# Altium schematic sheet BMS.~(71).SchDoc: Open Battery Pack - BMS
size A3; Date: 26/03/2019; Author: Morgane Vallée - Samuel Lesueur; Revision: 1.0; SheetNumber: 1; SheetTotal: 3
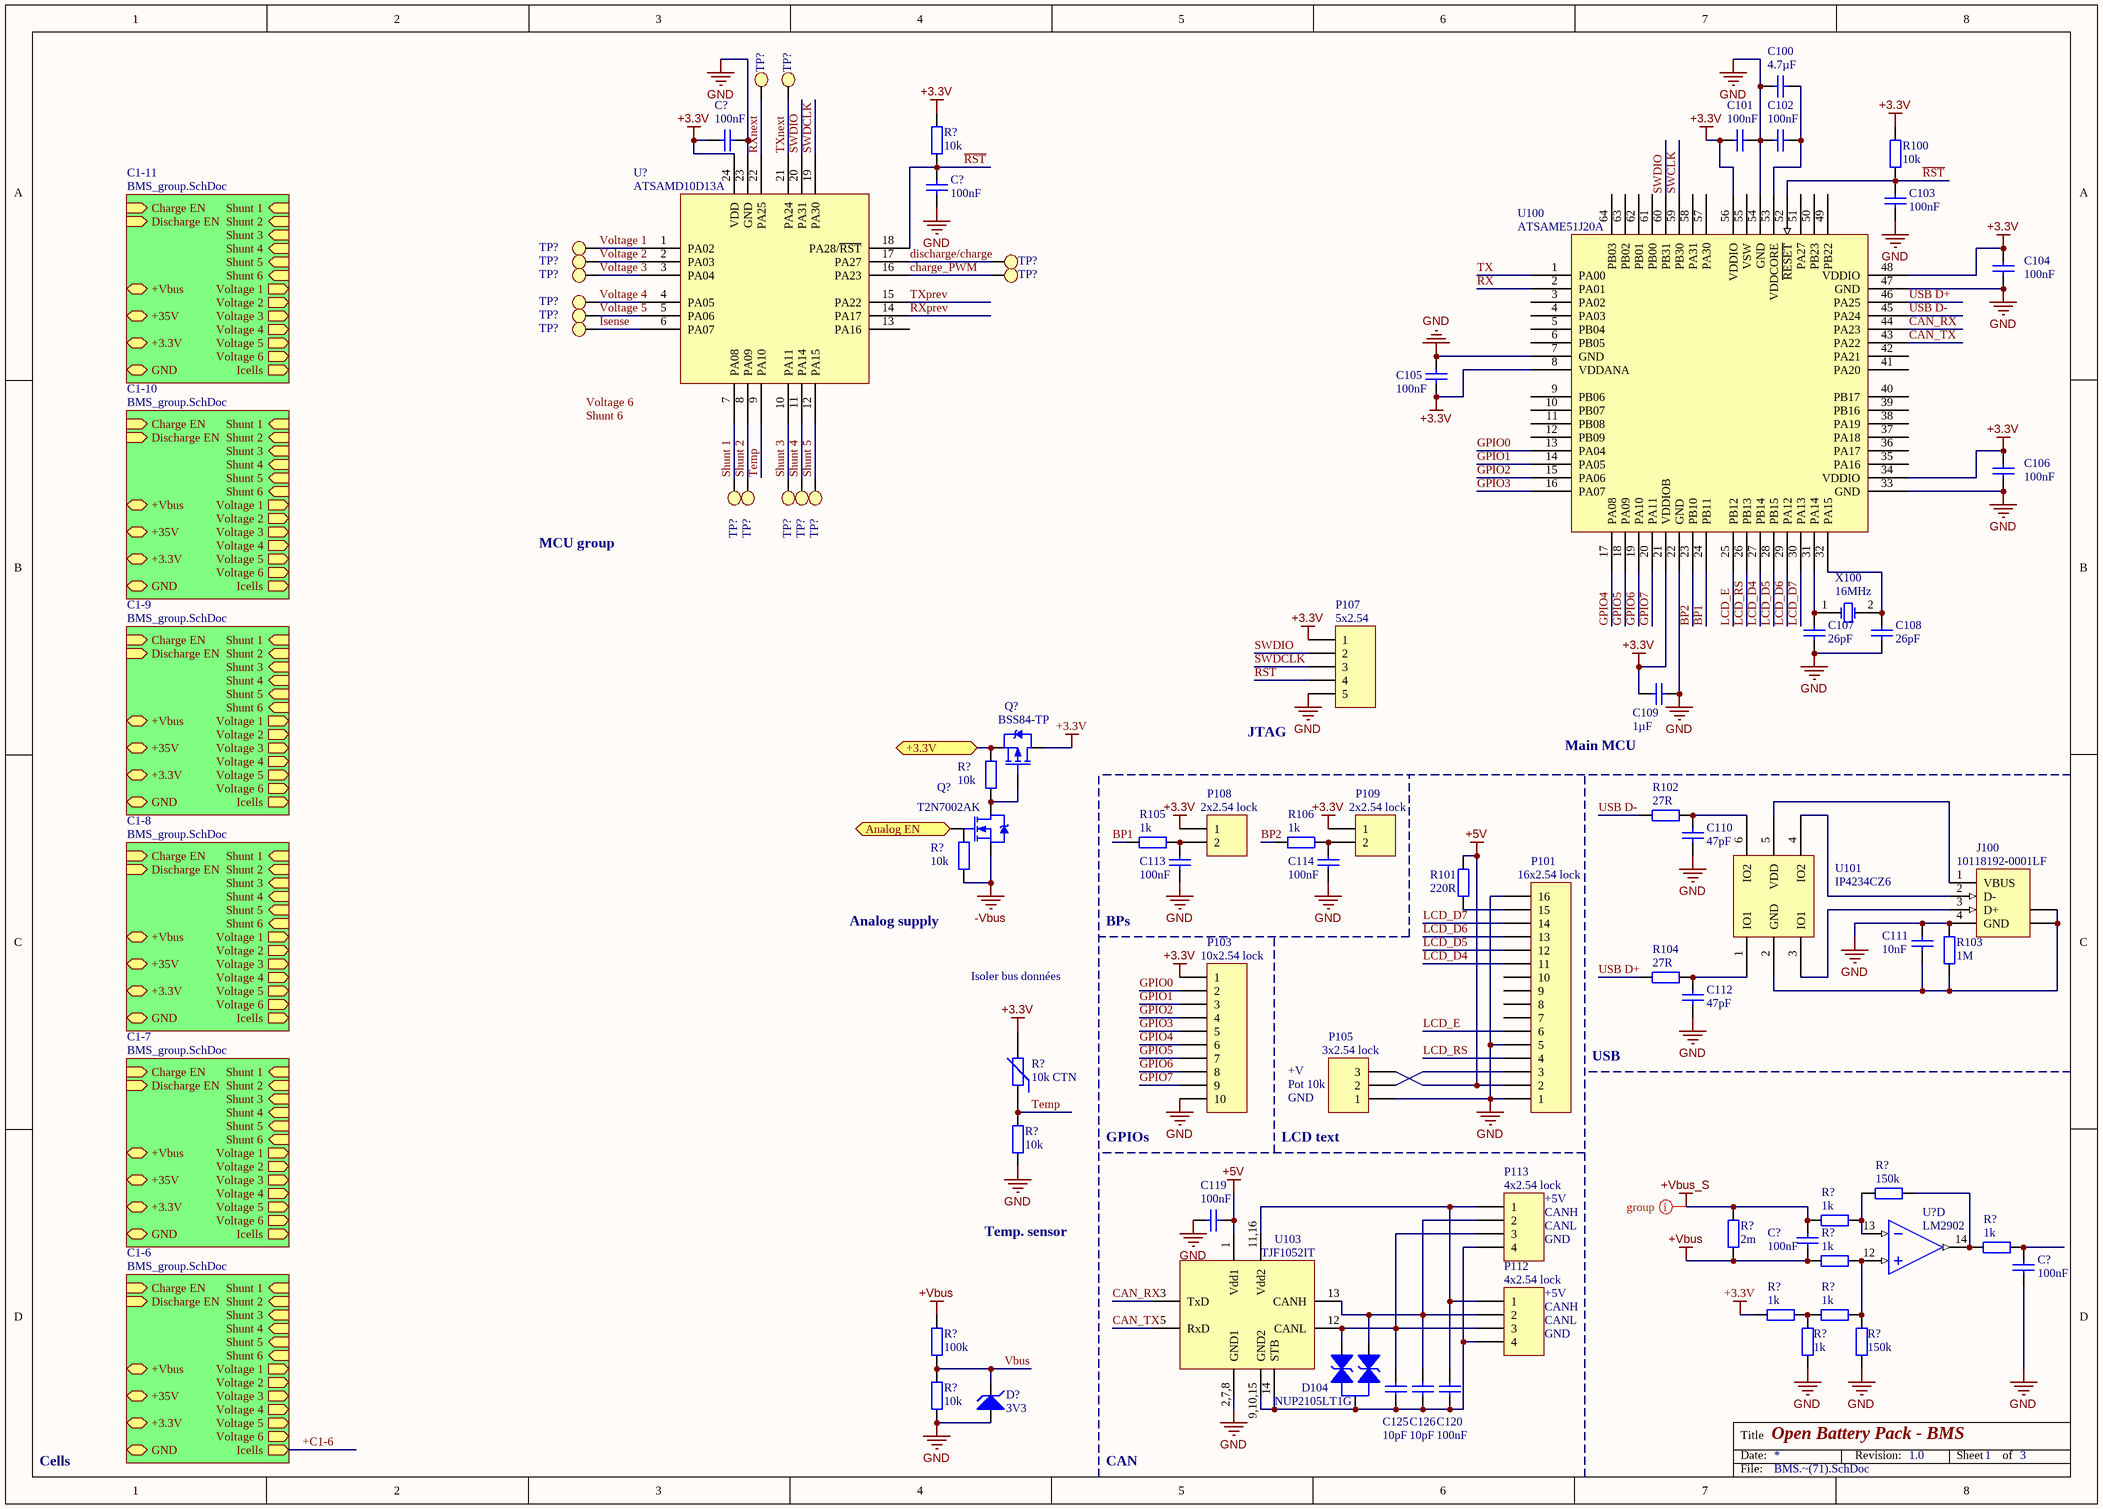
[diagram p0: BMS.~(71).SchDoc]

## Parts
(Parts that share a designator on the sheet are numbered #1, #2 ... from top to bottom, then left to right.)
C100  4.7µF  [C0603]
C101  100nF  [C0603]
C102  100nF  [C0603]
C103  100nF  [C0603]
C104  100nF  [C0603]
C105  100nF  [C0603]
C106  100nF  [C0603]
C107  26pF  [C0603]
C108  26pF  [C0603]
C109  1µF  [C0603]
C110  47pF  [C0603]
C111  10nF  [C0603]
C112  47pF  [C0603]
C113  100nF  [C0603]
C114  100nF  [C0603]
C119  100nF  [C0603]
C120  100nF  [C0603]
C125  10pF  [C0603]
C126  10pF  [C0603]
C?#1  100nF  [C0603]
C?#2  100nF  [C0603]
C?#3  100nF  [C0603]
C?#4  100nF  [C0603]
D104  NUP2105LT1G  [DIODES SOT-23-3]
D?  3V3  [DIODE-0.7]
J100  10118192-0001LF  [FCI USB 10118193-0001LF]
P101  16x2.54 lock  [HDR1X16]
P103  10x2.54 lock  [MOLEX KK 0022272101]
P105  3x2.54 lock  [MOLEX KK 0022272031]
P107  5x2.54  [HDR1X5]
P108  2x2.54 lock  [MOLEX KK 0022272021]
P109  2x2.54 lock  [MOLEX KK 0022272021]
P112  4x2.54 lock  [MOLEX SDA-70553-4PIN]
P113  4x2.54 lock  [MOLEX SDA-70553-4PIN]
Q?#1  BSS84-TP  [DIODES SOT-23-3]
Q?#2  T2N7002AK  [DIODES SOT-23-3]
R100  10k  [R0603]
R101  220R  [R0603]
R102  27R  [R0603]
R103  1M  [R0603]
R104  27R  [R0603]
R105  1k  [R0603]
R106  1k  [R0603]
R?#1  10k  [R0603]
R?#2  10k  [R0603]
R?#3  10k  [R0603]
R?#4  10k CTN  [NTC 0402/1005]
R?#5  10k  [R0603]
R?#6  1k  [R0603]
R?#7  150k  [R0603]
R?#8  2m  [R1206]
R?#9  1k  [R0603]
R?#10  1k  [R0603]
R?#11  100k  [R0603]
R?#12  1k  [R0603]
R?#13  1k  [R0603]
R?#14  1k  [R0603]
R?#15  150k  [R0603]
R?#16  10k  [R0603]
TP?#1  Test Point  [Test Point]  (value not drawn)
TP?#2  Test Point  [Test Point]  (value not drawn)
TP?#3  Test Point  [Test Point]  (value not drawn)
TP?#4  Test Point  [Test Point]  (value not drawn)
TP?#5  Test Point  [Test Point]  (value not drawn)
TP?#6  Test Point  [Test Point]  (value not drawn)
TP?#7  Test Point  [Test Point]  (value not drawn)
TP?#8  Test Point  [Test Point]  (value not drawn)
TP?#9  Test Point  [Test Point]  (value not drawn)
TP?#10  Test Point  [Test Point]  (value not drawn)
TP?#11  Test Point  [Test Point]  (value not drawn)
TP?#12  Test Point  [Test Point]  (value not drawn)
TP?#13  Test Point  [Test Point]  (value not drawn)
TP?#14  Test Point  [Test Point]  (value not drawn)
TP?#15  Test Point  [Test Point]  (value not drawn)
U100  ATSAME51J20A  [TQFP-64N]
U101  IP4234CZ6  [VISHAY TSOP-6 MO-193C]
U103  TJF1052IT  [SI LABS SOIC-16 WIDE]
U?#1  ATSAMD10D13A  [SMSC QFN-24 4x4MM]
U?#2  LM2902  [Atmel SO-14 14S1]  (part D of 5)
X100  16MHz  [ABRACON ABLS]

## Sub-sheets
C1-6 = BMS_group.SchDoc: +Vbus, Shunt 1 (in), Shunt 2 (in), Shunt 3 (in), Shunt 4 (in), Shunt 5 (in), Shunt 6 (in), Voltage 1 (out), Voltage 2 (out), Voltage 3 (out), Voltage 4 (out), +3.3V, Voltage 5 (out), Voltage 6 (out), Charge EN (in), Discharge EN (in), Icells (out), GND, +35V
C1-7 = BMS_group.SchDoc: +Vbus, Shunt 1 (in), Shunt 2 (in), Shunt 3 (in), Shunt 4 (in), Shunt 5 (in), Shunt 6 (in), Voltage 1 (out), Voltage 2 (out), Voltage 3 (out), Voltage 4 (out), +3.3V, Voltage 5 (out), Voltage 6 (out), Charge EN (in), Discharge EN (in), Icells (out), GND, +35V
C1-8 = BMS_group.SchDoc: +Vbus, Shunt 1 (in), Shunt 2 (in), Shunt 3 (in), Shunt 4 (in), Shunt 5 (in), Shunt 6 (in), Voltage 1 (out), Voltage 2 (out), Voltage 3 (out), Voltage 4 (out), +3.3V, Voltage 5 (out), Voltage 6 (out), Charge EN (in), Discharge EN (in), Icells (out), GND, +35V
C1-9 = BMS_group.SchDoc: +Vbus, Shunt 1 (in), Shunt 2 (in), Shunt 3 (in), Shunt 4 (in), Shunt 5 (in), Shunt 6 (in), Voltage 1 (out), Voltage 2 (out), Voltage 3 (out), Voltage 4 (out), +3.3V, Voltage 5 (out), Voltage 6 (out), Charge EN (in), Discharge EN (in), Icells (out), GND, +35V
C1-10 = BMS_group.SchDoc: +Vbus, Shunt 1 (in), Shunt 2 (in), Shunt 3 (in), Shunt 4 (in), Shunt 5 (in), Shunt 6 (in), Voltage 1 (out), Voltage 2 (out), Voltage 3 (out), Voltage 4 (out), +3.3V, Voltage 5 (out), Voltage 6 (out), Charge EN (in), Discharge EN (in), Icells (out), GND, +35V
C1-11 = BMS_group.SchDoc: +Vbus, Shunt 1 (in), Shunt 2 (in), Shunt 3 (in), Shunt 4 (in), Shunt 5 (in), Shunt 6 (in), Voltage 1 (out), Voltage 2 (out), Voltage 3 (out), Voltage 4 (out), +3.3V, Voltage 5 (out), Voltage 6 (out), Charge EN (in), Discharge EN (in), Icells (out), GND, +35V

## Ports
+3.3V, Analog EN (in)

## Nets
+3.3V: C101.2 C104.2 C105.1 C106.2 C109.2 C?#1.2 P103.1 P107.1 P108.1 P109.1 Q?#1.3(D) R100.2 R?#1.2 R?#4.2 R?#12.2 U100.8(VDDANA) U100.21(VDDIOB) U100.34(VDDIO) U100.48(VDDIO) U100.56(VDDIO) U?#1.24(VDD)
+5V: C119.2 P101.2 P105.3 R101.2 U103.1(Vdd1)
+Vbus: C?#3.2 R?#8.1 R?#10.2 R?#11.1
+Vbus_S: C?#3.1 R?#6.1 R?#8.2
-Vbus: Q?#2.2(S) R?#3.1
GND: C100.2 C101.1 C102.2 C103.1 C104.1 C105.2 C106.1 C107.1 C108.1 C109.1 C110.1 C111.2 C112.1 C113.1 C114.1 C119.1 C?#1.1 C?#2.1 C?#4.2 D?.1(A) J100.4(GND) P101.1 P101.5 P101.16 P103.10 P105.1 P107.5 R103.1 R?#5.2 R?#13.2 R?#15.1 R?#16.2 U100.7(GND) U100.22(GND) U100.33(GND) U100.47(GND) U100.54(GND) U103.2,7,8(GND1) U?#1.23(GND)
+3.3V: Q?#1.2(S) R?#2.1 ; port +3.3V  [a separate net that carries the same name]
Analog EN: Q?#2.1(G) ; port Analog EN
BP1: R105.1 U100.24(PB11)
BP2: R106.1 U100.23(PB10)
CAN_RX: U100.44(PA23) U103.3(TxD)
CAN_TX: U100.43(PA22) U103.5(RxD)
charge_PWM: TP?#7.1 U?#1.16(PA23)
discharge/charge: TP?#5.1 U?#1.17(PA27)
GPIO0: P103.2 U100.13(PA04)
GPIO1: P103.3 U100.14(PA05)
GPIO2: P103.4 U100.15(PA06)
GPIO3: P103.5 U100.16(PA07)
GPIO4: P103.6 U100.17(PA08)
GPIO5: P103.7 U100.18(PA09)
GPIO6: P103.8 U100.19(PA10)
GPIO7: P103.9 U100.20(PA11)
Isense: TP?#10.1 U?#1.6(PA07)
LCD_D4: P101.11 U100.27(PB14)
LCD_D5: P101.12 U100.28(PB15)
LCD_D6: P101.13 U100.29(PA12)
LCD_D7: P101.14 U100.30(PA13)
LCD_E: P101.6 U100.25(PB12)
LCD_RS: P101.4 U100.26(PB13)
~{RST}: C103.2 C?#2.2 P107.4 R100.1 R?#1.1 U100.52(~{RESET}) U?#1.18(PA28/~{RST})
RX: U100.2(PA01)
RXnext: TP?#1.1 U?#1.22(PA25)
RXprev: U?#1.14(PA17)
Shunt 1: TP?#11.1 U?#1.7(PA08)
Shunt 2: TP?#12.1 U?#1.8(PA09)
Shunt 3: TP?#13.1 U?#1.10(PA11)
Shunt 4: TP?#14.1 U?#1.11(PA14)
Shunt 5: TP?#15.1 U?#1.12(PA15)
SWCLK: U100.59(PB30)
SWDCLK: P107.3 U?#1.19(PA30)
SWDIO: P107.2 U100.60(PB31) U?#1.20(PA31)
Temp: R?#4.1 R?#5.1 U?#1.9(PA10)
TX: U100.1(PA00)
TXnext: TP?#2.1 U?#1.21(PA24)
TXprev: U?#1.15(PA22)
USB D+: R104.1 U100.46(PA25)
USB D-: R102.1 U100.45(PA24)
Vbus: D?.2(K) R?#11.2 R?#16.1
Voltage 1: TP?#3.1 U?#1.1(PA02)
Voltage 2: TP?#4.1 U?#1.2(PA03)
Voltage 3: TP?#6.1 U?#1.3(PA04)
Voltage 4: TP?#8.1 U?#1.4(PA05)
Voltage 5: TP?#9.1 U?#1.5(PA06)
NetC100_1: C100.1 C102.1 U100.53(VDDCORE)
NetC107_2: C107.2 U100.31(PA14) X100.1(OSC1)
NetC108_2: C108.2 U100.32(PA15) X100.2(OSC2)
NetC110_2: C110.2 R102.2 U101.6(IO2)
NetC111_1: C111.1 J100.5(SHLD) J100.6(SHLD) R103.2 U101.2(GND)
NetC112_2: C112.2 R104.2 U101.1(IO1)
NetC113_2: C113.2 P108.2 R105.2
NetC114_2: C114.2 P109.2 R106.2
NetC120_1: C120.1 C125.1 C126.1 D104.3 P112.4 P113.4 U103.9,10,15(GND2) U103.14(STB)
NetC120_2: C120.2 P112.1 P113.1 U103.11,16(Vdd2)
NetC125_2: C125.2 D104.2 P112.3 P113.3 U103.12(CANL)
NetC126_2: C126.2 D104.1 P112.2 P113.2 U103.13(CANH)
NetC?#4_1: C?#4.1 R?#9.1
NetJ100_1: J100.1(VBUS) U101.5(VDD)
NetJ100_2: J100.2(D-) U101.4(IO2)
NetJ100_3: J100.3(D+) U101.3(IO1)
NetP101_3: P101.3 P105.2
NetP101_15: P101.15 R101.1
NetQ?#1_1: Q?#1.1(G) Q?#2.3(D) R?#2.2
NetR?#6_2: R?#6.2 R?#7.2 U?#2.13(IN-)
NetR?#7_1: R?#7.1 R?#9.2 U?#2.14(OUT)
NetR?#10_1: R?#10.1 R?#14.1 R?#15.2 U?#2.12(IN+)
NetR?#12_1: R?#12.1 R?#13.1 R?#14.2

Not connected (* = marked no-connect by the designer): P101 7 8 9 10; R?#3 2; U100 3(PA02) 4(PA03) 5(PB04) 6(PB05) 9(PB06) 10(PB07) 11(PB08) 12(PB09) 35(PA16) 36(PA17) 37(PA18) 38(PA19) 39(PB16) 40(PB17) 41(PA20) 42(PA21) 49(PB22) 50(PB23) 51(PA27) 55(VSW) 57(PA30) 58(PA31) 61(PB00) 62(PB01) 63(PB02) 64(PB03); U?#1 13(PA16)

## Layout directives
net class Group: +Vbus_S

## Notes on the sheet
- MCU group
- JTAG
- Main MCU
- Analog supply
- Isoler bus données
- BPs
- (near P105) Pot 10k
- GND
- +V
- USB
- GPIOs
- (near P105) LCD text
- Temp. sensor
- (near P113) +5V
- (near P113) CANH
- (near P113) CANL
- (near P113) GND
- +5V
- (near P112) CANH
- (near P112) CANL
- (near P112) GND
- Cells
- CAN
- Labels drawn without touching a wire or pin: Shunt 6, Voltage 6

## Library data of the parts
C100-C114 C119 C120 C125 C126 C?#1-C?#4 = Cap: Capacitor
D104 = Dual Line TVS
D? = Diode Zener
J100 = 1-353576-1: USB 1.1, Right Angle, SMT, A Type, Receptacle, 4 Position, White; pin to pad: 4>5 5>S 6>S
P101 = Header 16: Header, 16-Pin
P103 = Header 10: Header, 10-Pin
P105 = Header 3: Header, 3-Pin
P107 = Header 5: Header, 5-Pin
P108 P109 = Header 2: Header, 2-Pin
P112 P113 = Header 4H: Header, 4-Pin, Right Angle
Q?#1 = MOSFET_P
Q?#2 = MOSFET_N
R100-R106 R?#1-R?#3 R?#5-R?#16 = Res2: Resistor
R?#4 = Res Varistor: Varistor (Voltage-Sensitive Resistor)
U101 = IP4234CZ6: Single USB 2.0 ESD protection to IEC 61000-4-2 level 4
U103 = TJF1052IT: Galvanically isolated high-speed CAN transceiver
U?#2 = LM2902: Low-power quad operational amplifiers
X100 = XTAL: Crystal Oscillator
